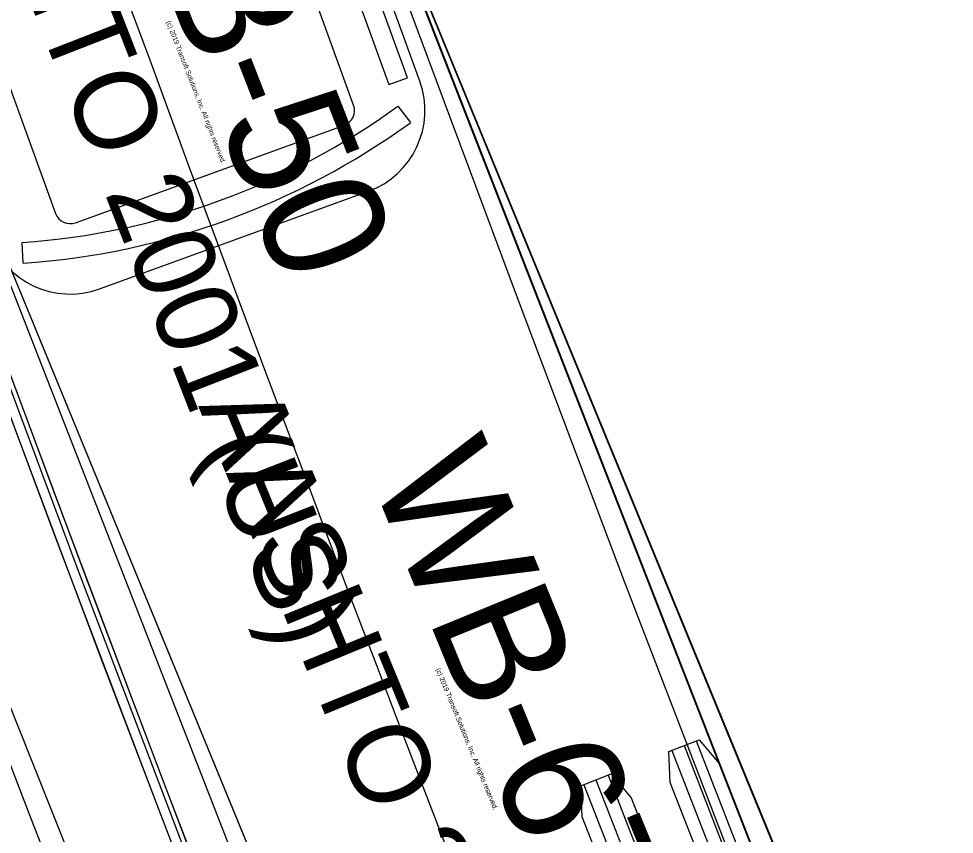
# Model space of a CAD drawing. Extents: x 1639988 to 1641860, y 841974 to 844187.
# Drawn here: x 1640205.28 to 1640221.62, y 844112.88 to 844127.13 of the extents above; entities that cross this region are included whole.
import ezdxf

# ---------------------------------------------------------------- set-up
doc = ezdxf.new("R2010")
doc.units = 0
for name, color, linetype in [('Scratch_Level_1', 7, 'Continuous'), ('Scratch_Level_2', 7, 'Continuous'), ('Scratch_Level_3', 7, 'Continuous'), ('Scratch_Level_4', 7, 'Continuous'), ('Scratch_Level_5', 7, 'Continuous'), ('Scratch_Level_6', 7, 'Continuous')]:
    doc.layers.add(name, color=color, linetype=linetype)

msp = doc.modelspace()

# ---------------------------------------------------------------- linework, layer by layer
at = {"layer": 'Scratch_Level_1'}
for p, q in [((1640220.202, 844107.217), (1640204.762, 844146.813)), ((1640196.843, 844143.725), (1640212.283, 844104.129)), ((1640217.112, 844114.509), (1640218.444, 844111.093)), ((1640216.685, 844114.343), (1640218.017, 844110.927)), ((1640216.899, 844114.426), (1640218.231, 844111.01)), ((1640215.361, 844113.827), (1640216.694, 844110.411)), ((1640215.575, 844113.91), (1640216.907, 844110.494)), ((1640215.148, 844113.744), (1640216.48, 844110.327))]:
    msp.add_line(p, q, dxfattribs=at)
for points in [[(1640177.815, 844187.311), (1640188.919, 844157.376), (1640192.648, 844147.427), (1640196.411, 844137.497), (1640200.22, 844127.592), (1640204.089, 844117.705), (1640228.263, 844057.033)], [(1640200.563, 844158.427), (1640204.547, 844146.924), (1640204.762, 844146.813), (1640220.203, 844107.235), (1640222.166, 844102.297), (1640224.155, 844097.371), (1640226.171, 844092.456), (1640228.214, 844087.553), (1640230.284, 844082.66)], [(1640220.307, 844082.415), (1640218.24, 844087.364), (1640216.2, 844092.323), (1640214.186, 844097.294), (1640212.199, 844102.274), (1640210.121, 844107.569), (1640208.206, 844112.529), (1640206.319, 844117.491), (1640204.459, 844122.464), (1640202.625, 844127.447), (1640200.818, 844132.44), (1640199.024, 844137.479), (1640196.843, 844143.725), (1640197.043, 844143.873), (1640195.321, 844148.9)]]:
    msp.add_lwpolyline(points, dxfattribs=at)
for points in [[(1640216.632, 844114.322), (1640217.165, 844114.53), (1640217.512, 844114.114), (1640218.471, 844111.655), (1640218.497, 844111.114), (1640217.964, 844110.906), (1640217.617, 844111.322), (1640216.658, 844113.781)], [(1640215.095, 844113.723), (1640215.628, 844113.931), (1640215.975, 844113.515), (1640216.934, 844111.055), (1640216.96, 844110.515), (1640216.427, 844110.307), (1640216.08, 844110.722), (1640215.121, 844113.182)]]:
    msp.add_lwpolyline(points, close=True, dxfattribs=at)
for radius, start, end in [(994, 198.505393, 206.873019), (1005, 200.317507, 203.824551)]:
    msp.add_arc((1641140.378, 844469.766), radius, start, end, dxfattribs=at)
at = {"layer": 'Scratch_Level_2'}
for points in [[(1640177.811, 844187.321), (1640188.919, 844157.376), (1640192.648, 844147.427), (1640196.411, 844137.497), (1640200.22, 844127.592), (1640204.089, 844117.705), (1640228.263, 844057.033)], [(1640220.38, 844082.445), (1640218.314, 844087.392), (1640216.154, 844092.648), (1640214.158, 844097.58), (1640212.19, 844102.516), (1640210.249, 844107.464), (1640208.334, 844112.422), (1640206.445, 844117.391), (1640204.582, 844122.37), (1640202.745, 844127.361), (1640200.909, 844132.432), (1640199.257, 844137.07), (1640199.32, 844137.222), (1640197.553, 844142.266), (1640195.83, 844147.27), (1640194.126, 844152.304), (1640192.663, 844156.699), (1640200.197, 844159.388), (1640205.316, 844145.036), (1640206.939, 844140.402), (1640207.119, 844140.301), (1640227.327, 844091.148), (1640229.381, 844086.251), (1640231.462, 844081.368)], [(1640227.214, 844091.335), (1640227.234, 844091.343), (1640227.208, 844091.408), (1640225.054, 844096.65), (1640207.119, 844140.301), (1640203.188, 844138.686), (1640199.257, 844137.07), (1640217.192, 844093.42), (1640219.347, 844088.178), (1640219.374, 844088.113), (1640219.394, 844088.121)]]:
    msp.add_lwpolyline(points, dxfattribs=at)
for radius, start, end in [(994, 198.505393, 206.873019), (1005, 200.317507, 203.824551)]:
    msp.add_arc((1641140.378, 844469.766), radius, start, end, dxfattribs=at)
at = {"layer": 'Scratch_Level_3'}
for points in [[(1640177.809, 844187.326), (1640188.919, 844157.376), (1640192.648, 844147.427), (1640196.411, 844137.497), (1640200.22, 844127.592), (1640204.089, 844117.705), (1640228.263, 844057.033)], [(1640219.861, 844083.681), (1640217.802, 844088.63), (1640215.645, 844093.899), (1640213.642, 844098.867), (1640211.667, 844103.843), (1640209.719, 844108.829), (1640207.797, 844113.826), (1640205.902, 844118.835), (1640204.033, 844123.854), (1640202.184, 844128.901), (1640199.257, 844137.071), (1640199.32, 844137.222), (1640197.553, 844142.266), (1640195.83, 844147.27), (1640194.126, 844152.304), (1640192.663, 844156.699), (1640200.197, 844159.388), (1640205.316, 844145.036), (1640206.939, 844140.403), (1640207.119, 844140.301), (1640227.452, 844090.84), (1640229.508, 844085.945)], [(1640227.213, 844091.334), (1640227.232, 844091.342), (1640227.206, 844091.407), (1640225.053, 844096.649), (1640207.119, 844140.301), (1640203.188, 844138.686), (1640199.257, 844137.071), (1640217.19, 844093.419), (1640219.345, 844088.178), (1640219.372, 844088.112), (1640219.392, 844088.12)]]:
    msp.add_lwpolyline(points, dxfattribs=at)
for radius, start, end in [(994, 198.505393, 206.873019), (1005, 200.317507, 203.824551)]:
    msp.add_arc((1641140.378, 844469.766), radius, start, end, dxfattribs=at)
at = {"layer": 'Scratch_Level_4'}
for p, q in [((1640211.128, 844125.613), (1640198.694, 844159.857)), ((1640193.488, 844157.967), (1640205.923, 844123.723)), ((1640206.269, 844123.561), (1640210.967, 844125.267))]:
    msp.add_line(p, q, dxfattribs=at)
for points in [[(1640199.38, 844162.307), (1640212.128, 844127.237), (1640213.982, 844122.255), (1640215.862, 844117.284), (1640217.769, 844112.323), (1640219.703, 844107.372), (1640221.663, 844102.432), (1640223.649, 844097.502), (1640225.662, 844092.583), (1640227.702, 844087.676), (1640229.768, 844082.779)], [(1640212.284, 844126.033), (1640210.712, 844130.363), (1640210.899, 844130.583), (1640209.705, 844133.873), (1640209.42, 844133.922), (1640202.234, 844153.711), (1640202.366, 844154.082), (1640201.172, 844157.372), (1640200.832, 844157.571)], [(1640190.54, 844152.943), (1640197.954, 844132.962), (1640201.698, 844123.028), (1640205.503, 844113.126), (1640207.434, 844108.188), (1640209.385, 844103.259), (1640211.358, 844098.34), (1640213.353, 844093.431), (1640215.372, 844088.529), (1640219.496, 844078.72)], [(1640219.769, 844083.264), (1640217.707, 844088.215), (1640215.671, 844093.176), (1640213.661, 844098.149), (1640211.678, 844103.133), (1640209.723, 844108.127), (1640207.793, 844113.131), (1640205.891, 844118.146), (1640204.016, 844123.17), (1640202.17, 844128.2), (1640200.243, 844133.54), (1640198.46, 844138.567), (1640196.705, 844143.604), (1640194.97, 844148.666)], [(1640211.902, 844125.598), (1640212.12, 844125.31)], [(1640206.689, 844122.405), (1640211.386, 844124.111)], [(1640205.357, 844122.854), (1640205.339, 844123.215)]]:
    msp.add_lwpolyline(points, dxfattribs=at)
msp.add_lwpolyline([(1640211.743, 844125.976), (1640212.067, 844126.094), (1640210.033, 844131.696), (1640209.709, 844131.577)], close=True, dxfattribs=at)
for centre, radius, start, end in [((1641140.378, 844469.766), 994, 198.505393, 206.873019), ((1640210.874, 844125.521), 1.5, 289.9568, 19.9568), ((1640204.449, 844135.895), 12.711, 274.014, 305.8996), ((1640210.874, 844125.521), 0.27, 289.9568, 19.9568), ((1640204.449, 844135.895), 13.073, 273.9839, 305.9297), ((1640206.177, 844123.815), 0.27, 199.9568, 289.9568), ((1640206.177, 844123.815), 1.5, 199.9568, 289.9568), ((1641140.378, 844469.766), 1005, 200.317507, 203.824551)]:
    msp.add_arc(centre, radius, start, end, dxfattribs=at)
at = {"layer": 'Scratch_Level_5'}
for p, q in [((1640211.128, 844125.613), (1640198.694, 844159.857)), ((1640193.488, 844157.967), (1640205.923, 844123.723)), ((1640206.269, 844123.561), (1640210.967, 844125.267))]:
    msp.add_line(p, q, dxfattribs=at)
for points in [[(1640199.38, 844162.307), (1640212.128, 844127.237), (1640213.982, 844122.255), (1640215.862, 844117.284), (1640217.769, 844112.323), (1640219.703, 844107.372), (1640221.663, 844102.432), (1640223.649, 844097.502), (1640225.662, 844092.583), (1640227.702, 844087.676), (1640229.768, 844082.779)], [(1640212.284, 844126.033), (1640210.712, 844130.363), (1640210.899, 844130.583), (1640209.705, 844133.873), (1640209.42, 844133.922), (1640202.234, 844153.711), (1640202.366, 844154.082), (1640201.172, 844157.372), (1640200.832, 844157.571)], [(1640190.528, 844152.975), (1640197.954, 844132.962), (1640201.698, 844123.028), (1640205.503, 844113.126), (1640207.434, 844108.188), (1640209.385, 844103.259), (1640211.358, 844098.34), (1640213.353, 844093.431), (1640215.372, 844088.529), (1640219.496, 844078.72)], [(1640220.68, 844081.101), (1640218.606, 844086.047), (1640216.558, 844091.004), (1640214.537, 844095.972), (1640212.543, 844100.951), (1640210.575, 844105.941), (1640208.634, 844110.94), (1640206.72, 844115.951), (1640204.833, 844120.971), (1640202.974, 844125.999), (1640201.032, 844131.341), (1640199.237, 844136.367), (1640197.469, 844141.399), (1640195.728, 844146.442), (1640194.003, 844151.528)], [(1640211.902, 844125.598), (1640212.12, 844125.31)], [(1640206.689, 844122.405), (1640211.386, 844124.111)], [(1640205.357, 844122.854), (1640205.339, 844123.215)]]:
    msp.add_lwpolyline(points, dxfattribs=at)
msp.add_lwpolyline([(1640211.743, 844125.976), (1640212.067, 844126.094), (1640210.033, 844131.696), (1640209.709, 844131.577)], close=True, dxfattribs=at)
for centre, radius, start, end in [((1641140.378, 844469.766), 994, 198.505393, 206.873019), ((1640210.874, 844125.521), 1.5, 289.9568, 19.9568), ((1640204.449, 844135.895), 12.711, 274.014, 305.8995), ((1640210.874, 844125.521), 0.27, 289.9568, 19.9568), ((1640204.449, 844135.895), 13.073, 273.9839, 305.9297), ((1640206.177, 844123.815), 0.27, 199.9568, 289.9568), ((1640206.177, 844123.815), 1.5, 199.9568, 289.9568), ((1641140.378, 844469.766), 1005, 200.317507, 203.824551)]:
    msp.add_arc(centre, radius, start, end, dxfattribs=at)
at = {"layer": 'Scratch_Level_6'}
for p, q in [((1640211.128, 844125.613), (1640198.694, 844159.857)), ((1640193.488, 844157.967), (1640205.923, 844123.723)), ((1640206.269, 844123.561), (1640210.967, 844125.267))]:
    msp.add_line(p, q, dxfattribs=at)
for points in [[(1640199.38, 844162.307), (1640212.128, 844127.237), (1640213.982, 844122.255), (1640215.862, 844117.284), (1640217.769, 844112.323), (1640219.703, 844107.372), (1640221.663, 844102.432), (1640223.649, 844097.502), (1640225.662, 844092.583), (1640227.702, 844087.676), (1640229.768, 844082.779)], [(1640212.284, 844126.033), (1640210.712, 844130.363), (1640210.899, 844130.583), (1640209.705, 844133.873), (1640209.42, 844133.922), (1640202.234, 844153.711), (1640202.366, 844154.082), (1640201.172, 844157.372), (1640200.832, 844157.571)], [(1640190.518, 844153.001), (1640197.954, 844132.962), (1640201.698, 844123.028), (1640205.503, 844113.126), (1640207.434, 844108.188), (1640209.385, 844103.259), (1640211.358, 844098.34), (1640213.353, 844093.431), (1640215.372, 844088.529), (1640219.496, 844078.72)], [(1640220.68, 844081.101), (1640218.606, 844086.047), (1640216.558, 844091.004), (1640214.537, 844095.972), (1640212.543, 844100.951), (1640210.575, 844105.941), (1640208.634, 844110.94), (1640206.72, 844115.951), (1640204.833, 844120.971), (1640202.974, 844125.999), (1640201.032, 844131.341), (1640199.237, 844136.367), (1640197.469, 844141.399), (1640195.728, 844146.442), (1640194.003, 844151.528)], [(1640211.902, 844125.598), (1640212.12, 844125.31)], [(1640206.689, 844122.405), (1640211.386, 844124.111)], [(1640205.357, 844122.854), (1640205.339, 844123.215)]]:
    msp.add_lwpolyline(points, dxfattribs=at)
msp.add_lwpolyline([(1640211.743, 844125.976), (1640212.067, 844126.094), (1640210.033, 844131.696), (1640209.709, 844131.577)], close=True, dxfattribs=at)
for centre, radius, start, end in [((1641140.378, 844469.766), 994, 198.505393, 206.873019), ((1640210.874, 844125.521), 1.5, 289.9568, 19.9568), ((1640204.449, 844135.895), 12.711, 274.014, 305.8995), ((1640210.874, 844125.521), 0.27, 289.9568, 19.9568), ((1640204.449, 844135.895), 13.073, 273.9839, 305.9297), ((1640206.177, 844123.815), 0.27, 199.9568, 289.9568), ((1640206.177, 844123.815), 1.5, 199.9568, 289.9568), ((1641140.378, 844469.766), 1005, 200.317507, 203.824551)]:
    msp.add_arc(centre, radius, start, end, dxfattribs=at)

# ---------------------------------------------------------------- texts
at = {"layer": 'Scratch_Level_1'}
for s, height, p in [('AASHTO 2001 (US)', 1.41667, (1640203.751, 844131.838)), ('WB-50', 2.125, (1640206.751, 844130.482)), ('(c) 2019 Transoft Solutions, Inc. All rights reserved.', 0.085, (1640207.853, 844127.07))]:
    msp.add_text(s, height=height, rotation=291.3021, dxfattribs=at).set_placement(p)
at = {"layer": 'Scratch_Level_2'}
for s, height, p in [('AASHTO 2011 (US)', 1.41667, (1640208.412, 844120.36)), ('WB-67', 2.125, (1640211.398, 844119.153)), ('(c) 2019 Transoft Solutions, Inc. All rights reserved.', 0.085, (1640212.562, 844115.76))]:
    msp.add_text(s, height=height, rotation=292.3371, dxfattribs=at).set_placement(p)
at = {"layer": 'Scratch_Level_3'}
for s, height, p in [('AASHTO 2011 (US)', 1.41667, (1640208.412, 844120.36)), ('WB-67', 2.125, (1640211.397, 844119.152)), ('(c) 2019 Transoft Solutions, Inc. All rights reserved.', 0.085, (1640212.561, 844115.76))]:
    msp.add_text(s, height=height, rotation=292.3347, dxfattribs=at).set_placement(p)

doc.saveas('drawing.dxf')
